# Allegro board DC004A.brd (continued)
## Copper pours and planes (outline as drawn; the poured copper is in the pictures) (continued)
5VIN on L06_PWR-1: 38.73,22.99 35.43,26.29 26.8,26.29 26.8,29.59 25.27,31.11 25.27,34.04 33.78,34.04 34.16,34.42 34.16,58.93 33.91,59.18 4.06,59.18 1.91,61.34 1.91,113.54 2.03,113.54 4.06,115.57 4.06,135.89 5.97,135.89 5.97,155.45 12.07,155.45 12.32,155.19 12.32,141.86 12.7,141.86 12.7,72.9 15.88,69.72 48.39,69.72 51.18,66.93 51.18,33.15 61.47,33.15 61.47,30.99 46.23,30.99 44.96,29.72 44.96,22.99
5VIN on L08_PWR-2: 26.43,30.1 25.53,30.1 25.53,33.15 25.97,33.15 26.15,33.33 26.15,33.5 36.67,33.5 38.17,32 40.64,32 45.21,27.43 45.21,5.71 36.96,5.71 36.95,5.72 36.95,25.11 27.24,25.11 26.43,25.92
+2.2V on TOP, L04_SIG-1: 67.44,23.11 62.36,23.11 61.21,24.26 61.21,27.3 62.99,27.3 62.99,25.53 63.25,25.27 67.56,25.27 67.56,27.56 64.64,27.56 64.64,28.96 67.56,28.96 67.56,33.02 70.74,36.2 70.74,37.97 72.9,40.13 77.34,40.13 77.47,40 77.47,34.04 73.53,34.04 73.53,28.19 77.09,28.19 77.09,22.9 75.56,22.9 75.56,19.81 67.44,19.81
+3.3V_LMX on TOP: 56.9,141.35 56.9,135.13 63.88,135.13 64.14,134.87 67.06,134.87 67.56,135.38 67.56,137.92 67.06,138.43 67.06,139.07 64.64,139.07 64.64,137.41 61.09,137.41 59.94,138.56 59.94,141.35
+3.3V_LMX on TOP: 37.34,133.35 37.34,128.78 40.51,128.78 40.51,133.35
+3.3V_LMX on L06_PWR-1: 46.1,140.72 53.21,140.72 54.99,142.49 56.77,142.49 59.94,145.67 63.63,145.67 63.63,141.73 63.25,141.35 59.94,141.35 59.94,138.56 61.09,137.41 64.64,137.41 64.64,139.07 67.06,139.07 67.06,138.43 67.56,137.92 67.56,135.89 66.8,135.13 52.96,135.13 52.96,135 47.5,135 40.51,128.02 36.2,128.02 36.2,130.81 ; 1 cut-out
+3.3V_LMX on L08_PWR-2: 62.61,133.6 60.58,135.64 58.42,135.64 57.91,136.14 57.91,137.03 57.52,137.42 57.52,139.92 56.51,140.93 55.57,140.93 55.25,141.25 55.25,143.76 56.87,145.39 71.88,145.39 71.88,133.6
+3.3V_LMXRF on TOP: 24.64,132.97 24.64,126.36 25.27,125.73 26.42,125.73 27.18,126.49 27.18,128.02 27.05,128.14 27.05,132.97
+3.3V_LMXRF on L06_PWR-1: 24.89,125.73 26.67,125.73 27.18,126.24 27.18,128.65 27.3,128.78 27.3,132.97 24.77,132.97 24.77,131.7 24.64,131.57 24.64,125.98
+3.3V_LMXRF on L08_PWR-2: 23.56,127.57 20.57,130.56 20.57,151.89 21.59,152.91 31.11,152.91 32.38,151.64 32.38,142.49 34.16,140.72 54.36,140.72 54.86,140.21 56.64,140.21 57.28,139.57 57.28,135.76 58.29,134.75 60.58,134.75 61.47,133.86 61.47,132.97 61.09,132.59 55.75,132.59 53.34,135 53.34,137.41 30.35,137.41 28.45,139.32 28.45,144.27 26.29,146.43 23.49,146.43 23.49,135.64 28.19,130.94 28.19,126.11 27.3,125.22 24.89,125.22 23.56,126.56
+3.3VCLK on TOP: 88.14,134.75 88.14,132.84 89.66,132.84 89.66,134.75
+3.3VCLK on TOP: 33.15,146.05 33.15,141.99 33.4,141.73 36.32,141.73 36.32,146.05
+3.3VCLK on TOP: 93.38,131.19 93.38,129.29 94.41,129.29 94.41,131.19
+3.3VCLK on TOP: 102.74,118.11 102.74,117.35 96.14,117.35 96.14,118.11
+3.3VCLK on TOP: 102.74,130.56 106.55,130.56 106.55,131.57 106.43,131.7 102.74,131.7
+3.3VCLK on TOP: 89.41,119.51 89.41,120.65 89.79,120.65 89.79,121.16 91.31,121.16 91.31,119.51
+3.3VCLK on L08_PWR-2: 87.12,113.66 87.12,119.25 87.01,119.37 87.01,124.74 85.87,125.88 77.32,125.88 77.22,125.98 77.22,127.51 77.47,127.76 77.47,139.87 80.14,142.54 80.14,143.76 80.14,143.76 80.14,146.05 46.23,146.05 41.53,141.35 33.91,141.35 33.15,142.11 33.15,146.05 34.54,147.45 36.45,147.45 43.31,154.31 85.47,154.31 93.81,145.96 105.37,145.96 108.71,142.62 108.71,123.7 107.82,122.81 107.82,113.66
GND on TOP (solid shape): 30.91,118.49 31.94,117.61 32.97,118.49 32.97,119 36.5,119 36.5,109.86 34.49,109.86 34.49,110.36 33.45,111.3 32.41,110.36 32.41,109.86 31.44,109.86 31.44,110.36 30.41,111.26 29.39,110.36 29.39,109.86 27.35,109.86 27.35,119 30.91,119
GND on TOP (solid shape): 29.36,81.15 30.4,80.22 31.44,81.15 31.44,81.66 32.26,81.66 33.4,80.24 34.54,81.66 36.5,81.66 36.5,72.52 32.94,72.52 32.94,73.03 31.91,73.91 30.88,73.03 30.88,72.52 27.35,72.52 27.35,81.66 29.36,81.66
GND on TOP: 60.45,141.22 60.45,137.67 63.88,137.67 63.88,141.22
GND on TOP: 12.95,146.18 12.95,156.08 21.08,156.08 21.08,153.04 23.75,153.04 23.75,151.77 21.08,151.77 21.08,146.18
GND on TOP: 7,42.48 7,41.84 9.35,41.84 9.35,42.48
GND on TOP: 39.24,2.03 39.24,3.43 38.48,4.19 38.48,7.62 40.39,7.62 40.39,6.6 46.61,6.6 46.61,14.99 43.18,14.99 43.18,16.26 55.37,16.26 55.37,2.03
GND on TOP: 1.27,37.59 1.27,42.55 9.4,42.55 9.4,37.59
GND on TOP: 94.51,128.8 94.51,128.73 94.14,128.36 94.14,120.97 94.23,120.87 95.19,120.87 95.54,121.22 102.28,121.22 102.45,121.39 102.45,122.02 101.98,122.49 101.98,128.82 94.53,128.82
GND on TOP: 80.26,21.97 80.26,23.75 83.57,23.75 83.57,32.64 92.96,32.64 92.96,21.97
GND on TOP: 39.24,18.03 39.24,21.72 38.35,21.72 38.35,23.75 40.51,23.75 40.51,22.61 46.61,22.61 46.61,30.99 43.18,30.99 43.18,32.26 55.37,32.26 55.37,18.03
GND on TOP: 13.72,131.95 13.72,141.86 21.84,141.86 21.84,138.81 24.51,138.81 24.51,137.54 21.84,137.54 21.84,131.95
GND on TOP: 0.38,47.24 0.38,49.45 0.38,49.45 0.38,54.36 9.27,54.36 9.27,47.24
GND on TOP: 80.26,0.89 80.26,2.67 83.57,2.67 83.57,11.56 92.96,11.56 92.96,0.89
GND on BOTTOM: 15.14,92.31 15.14,89.14 17.82,89.14 17.82,92.31
GND on BOTTOM: 25.48,88.54 25.48,90.83 27.97,90.83 27.97,101.52 29.97,101.52 29.97,102.97 33.86,102.97 33.86,101.52 36.2,101.52 36.2,100.46 39.45,100.46 39.45,101.52 40.97,101.52 40.97,100.2 39.57,100.2 39.57,90.37 39.04,90.37 39.04,90.02 33.76,90.02 33.76,88.54 ; 2 cut-outs
GND on BOTTOM: 40.67,100.81 40.67,103.3 41.17,103.3 41.17,103.94 43.76,103.94 43.76,102.82 42.01,102.82 42.01,100.81
GND on BOTTOM: 55.58,64.7 55.58,57.79 62.12,57.79 62.12,57.79 63.92,57.79 63.92,59.38 62.12,59.38 62.12,64.7 59.52,64.7 59.52,65.38 58.68,65.38 58.68,64.7
GND on L02_GND-1: 0.38,22.9 0.38,35.94 0.38,35.94 0.38,36.58 0.38,36.58 0.38,49.56 0,49.94 0,115.29 0.38,115.67 0.38,147.83 0.38,147.83 0.38,156.72 111.76,156.72 111.76,156.71 111.76,119.63 149.48,119.63 149.48,52.07 111.87,52.07 111.87,22.9 111.89,22.88 111.89,0.51 111.76,0.38 0.38,0.38 0.38,22.9 ; 20 cut-outs
GND on L03_GND-2: 0.38,49.53 0,49.91 0,115.29 0.38,115.67 0.38,147.83 0.38,147.83 0.38,156.59 111.63,156.59 111.76,156.46 111.76,119.63 149.48,119.63 149.48,52.07 111.92,52.07 111.92,0.41 111.89,0.38 0.51,0.38 0.38,0.51 0.38,0.51 ; 4 cut-outs
GND on L04_SIG-1: 37.34,86.23 36.99,86.58 36.99,93.4 37.78,94.2 37.78,99.32 36.71,100.39 36.71,102.81 36.86,102.96 36.83,103 36.83,104.65 37.21,105.03 40.87,105.03 43.81,102.09 43.81,88.77 41.28,86.23 ; 1 cut-out
GND on L05_GND-3: 0.38,49.61 0,49.99 0,115.29 0.38,115.67 0.38,147.83 0.38,147.83 0.38,156.59 111.76,156.59 111.76,119.63 149.48,119.63 149.48,52.07 111.92,52.07 111.92,0.67 111.89,0.63 0.64,0.63 0.38,0.89 ; 4 cut-outs
GND on L06_PWR-1: 116.46,53.34 116.46,55.88 80.9,55.88 80.9,94.61 47.88,94.61 47.88,107.95 19.3,107.95 19.3,122.55 47.88,122.55 47.88,129.54 70.1,129.54 70.1,147.32 38.35,147.32 38.35,156.21 111.38,156.21 111.38,118.75 149.48,118.75 149.48,53.34 ; 1 cut-out
GND on L07_GND-4: 0.38,49.53 0,49.91 0,115.29 0.38,115.67 0.38,147.83 0.38,147.83 0.38,156.59 111.63,156.59 111.76,156.46 111.76,119.63 149.48,119.63 149.48,52.07 111.92,52.07 111.92,0.41 111.89,0.38 0.51,0.38 0.38,0.51 0.38,0.51 ; 2 cut-outs
GND on L08_PWR-2: 117.6,52.83 117.6,78.74 90.42,78.74 90.42,111.12 117.6,111.12 117.6,118.87 149.1,118.87 149.1,52.83
GND on L08_PWR-2: 5.33,156.21 5.33,132.08 19.3,132.08 19.3,156.21
GND on L08_PWR-2: 47.24,1.27 47.24,29.21 53.59,29.21 53.59,1.27
GND on L08_PWR-2: 2.03,37.97 2.03,53.85 1.91,53.85 1.91,119.25 26.04,119.25 26.04,101.22 24.77,101.22 24.77,99.19 26.04,99.19 26.04,58.59 15.73,58.59 15.73,53.65 13.21,53.65 13.21,37.97
GND on L08_PWR-2: 0.89,22.22 0.89,0.63 35.81,0.63 35.81,22.22
GND on L09_GND-5: 0.38,49.61 0,49.99 0,115.29 0.38,115.67 0.38,147.83 0.38,147.83 0.38,156.59 111.76,156.59 111.76,119.63 149.48,119.63 149.48,52.07 111.92,52.07 111.92,0.67 111.89,0.63 0.64,0.63 0.38,0.89 ; 2 cut-outs
GND on L10_SIG-2: 37.78,99.32 37.78,94.2 36.99,93.4 36.99,86.58 37.34,86.23 41.28,86.23 43.81,88.77 43.81,102.09 42.77,103.13 42.53,103.37 41.4,103.37 40.88,103.89 37.72,103.89 37.72,103.88 37.21,103.37 36.84,103.37 36.83,103.38 36.83,103 36.86,102.96 36.71,102.81 36.71,100.39
GND on L11_GND-6: 0.38,49.6 0,49.98 0,115.29 0.38,115.67 0.38,147.83 0.38,147.83 0.38,156.72 111.76,156.72 111.76,156.71 111.76,119.63 149.48,119.63 149.48,52.07 111.92,52.07 111.92,0.54 111.76,0.38 0.38,0.38 0.38,0.38 ; 4 cut-outs
VBUS on TOP: 18.31,37.49 24.92,37.49 25.02,37.39 25.02,36.05 25.5,35.58 25.5,34.71 26.68,33.52 33.48,33.52 34.39,34.43 34.39,37.1 34.11,37.38 32.74,37.38 32.65,37.29 32.65,35.56 32.47,35.37 31.69,35.37 31.38,35.68 31.38,37.2 31.32,37.25 30.75,37.25 30.62,37.13 30.62,36.51 29.8,35.69 27.81,35.69 27.81,35.69 27.05,35.69 26.54,36.2 26.54,37.47 26.55,37.47 26.55,38.99 25.93,39.61 18.73,39.61 18.31,39.19
VDDD33 on TOP: 24.13,146.05 24.13,141.22 26.54,141.22 26.54,146.05
VDDD33 on TOP: 107.59,66.56 107.59,64.05 106.81,63.27 106.81,62.39 106.91,62.29 109.04,62.29 109.06,62.31 109.06,66.33 108.84,66.56
VDDD33 on TOP: 42.8,39.37 42.8,41.27 50.04,41.27 50.04,40 44.32,40 44.32,39.37
VDDD33 on L08_PWR-2: 70.74,103.25 63.5,110.49 52.2,110.49 41.66,121.03 41.66,125.6 43.05,125.6 43.94,124.71 45.85,124.71 45.85,126.36 44.58,127.64 38.48,127.64 37.97,127.13 32.64,127.13 32.64,121.28 27.43,121.28 27.05,120.9 24.26,120.9 23.88,121.28 5.71,121.28 5.71,128.65 6.86,129.79 19.18,129.79 21.08,127.89 28.7,127.89 28.7,131.19 24,135.89 24,145.92 24.07,145.99 25.97,145.99 28.07,143.89 28.07,139.19 30.1,137.16 34.04,137.16 35.05,136.14 40.89,136.14 56.39,120.65 56.39,120.52 74.93,120.52 74.93,120.4 78.61,120.4 85.22,113.79 85.22,77.09 111,77.09 111,57.66 85.85,57.66 85.85,63.88 85.6,64.14 78.87,64.14 78.36,63.63 78.36,61.34 77.34,60.32 77.34,58.29 76.71,57.66 75.44,57.66 70.48,52.7 52.71,52.7 52.71,44.32 52.58,44.2 46.36,44.2 45.47,43.31 45.47,41.91 49.91,41.91 49.91,40.39 49.78,40.26 45.47,40.26 45.47,36.96 46.1,36.32 46.1,34.99 43.37,34.99 41.15,37.21 41.15,49.78 44.96,53.59 45.47,53.59 45.47,63.88 45.59,64.01 48.01,64.01 49.53,65.53 49.53,70.61 50.04,71.12 70.74,71.12 ; 61 cut-outs
VDDD33 on L10_SIG-2: 73.99,69.27 73.99,67.45 74.76,67.45 74.76,69.27
VDDL19 on TOP: 84.96,38.35 84.96,40.51 83.44,40.51 83.44,42.16 87.88,42.16 87.88,40.51 87,40.51 87,38.35
VDDL19 on BOTTOM: 47.12,39.62 47.12,38.73 49.53,38.73 49.53,39.62
VDDL19 on L04_SIG-1: 87.55,71.94 87.55,68.09 83.51,64.06 83.51,61.54 82.66,60.69 80.6,60.69 80.14,61.15 80.14,62.61 80.16,62.63 80.16,64.23 80.15,64.23 80.15,65.53 78.55,67.14 77.25,67.14 75.84,68.54 74.32,68.54 73.67,67.89 72.44,67.89 72.32,68.02 72.32,70.68 73.37,71.73 74.93,71.73 75.45,71.21 80.54,71.21 81.5,72.17 81.53,72.14 87.35,72.14
VDDL19 on L08_PWR-2: 46.1,40 50.04,40 52.45,42.42 78.99,42.42 78.99,61.34 80.52,62.87 85.22,62.87 85.22,45.59 87.76,43.05 87.76,38.23 86.11,38.23 85.47,38.86 82.8,38.86 81.79,37.85 61.98,37.85 61.09,38.73 52.96,38.73 51.56,37.34 46.1,37.34
VDDL19 on L10_SIG-2: 72.78,71.08 72.78,69.19 74.06,69.19 74.06,71.08
VINA on TOP (solid shape): 32.24,120.9 32.12,120.86 32.06,120.74 32.06,120.61 31.79,120.61 31.79,120.74 31.73,120.86 31.61,120.9 31.61,123.7 32.24,123.7
VINB on TOP (solid shape): 32.06,70.77 32.12,70.66 32.24,70.61 32.24,67.82 31.61,67.82 31.61,70.61 31.73,70.66 31.79,70.77 31.79,70.91 32.06,70.91
1P8V_USB on BOTTOM: 62.48,63.51 62.48,65.41 59.94,65.41 59.94,65.69 58.05,65.69 58.05,65.41 54.48,65.41 54.48,69.22 63.75,69.22 63.75,65.53 66.67,65.53 66.67,59.56 63.13,59.56 63.13,63.51
1P8V_USB on L10_SIG-2: 50.14,69.22 64.94,69.22 66.72,67.44 66.72,59.25 65.46,57.99 51.66,57.99 49.36,60.3 49.36,68.43 ; 4 cut-outs
12P0V_RX on TOP: 140.11,68.16 140.11,64.7 141.41,64.7 141.41,68.16
DEVCLKIN on TOP (solid shape): 5.13,97.23 5.24,97.17 5.38,97.17 5.38,96.89 5.24,96.89 5.13,96.83 5.08,96.71 2.29,96.71 2.29,97.35 5.08,97.35
DEVCLKIN on TOP (solid shape): 15.98,96.65 14.86,96.65 14.74,96.82 14.53,96.89 14.52,96.89 14.52,97.17 14.53,97.17 14.74,97.23 14.86,97.41 15.98,97.41
MASTER_BYPASS on TOP, L04_SIG-1: 79.76,39.75 79.76,35.18 83.31,35.18 83.31,39.75
MASTER_BYPASS1 on L06_PWR-1: 80.9,44.96 88.52,44.96 88.52,43.94 80.9,43.94
SLAVE_BYPASS on L04_SIG-1: 80.01,15.49 80.01,18.54 83.06,18.54 83.06,14.22 77.72,14.22 77.72,15.49
SLAVE_BYPASS1 on TOP, L04_SIG-1: 85.09,14.86 90.93,14.86 90.93,17.4 89.53,17.4 89.53,18.92 92.2,18.92 92.2,13.08 85.09,13.08
V_BUS on BOTTOM: 26.92,40.77 26.92,37.72 30.35,37.72 30.35,40.77
V_BUS on L04_SIG-1: 26.88,40.58 26.88,37.83 30.23,37.83 30.23,40.58
VA11 on TOP, L08_PWR-2: 85.09,15.11 85.09,18.8 83.44,18.8 83.44,20.83 87.88,20.83 87.88,19.81 87,19.81 87,16.64 88.01,16.64 88.01,15.11
VA11 on BOTTOM: 15.37,85.6 19.94,85.6 19.94,87.88 18.41,87.88 18.41,88.52 15.37,88.52
VA11 on L06_PWR-1: 63.37,71.55 59.68,75.24 44.79,75.24 43.44,73.9 16.63,73.9 13.71,76.81 13.71,104.78 15.15,106.22 34.05,106.22 36.1,104.17 36.07,104.14 36.07,92.2 36.58,91.69 41.58,91.69 41.58,90.67 42.59,89.66 76.08,89.66 78.36,87.38 78.36,37.5 77.6,36.74 77.6,25.27 81.15,21.72 88.01,21.72 88.01,15.24 73.47,15.24 73.06,15.65 73.06,15.97 64.26,24.77 64.26,31.88 63.37,32.77 ; 5 cut-outs
VA19 on TOP: 94.74,40.51 94.74,36.32 97.66,36.32 97.66,49.78 80.64,49.78 80.64,47.75 80.77,47.62 94.87,47.62 94.87,40.51
VA19 on BOTTOM: 29.15,88.13 26.8,88.13 26.8,84.87 29.15,84.87
VA19 on L06_PWR-1: 16.38,47.12 24.38,47.12 24.38,46.99 29.59,46.99 29.59,42.42 24.38,42.42 24.38,14.73 90.17,14.73 90.17,20.45 92.84,23.11 92.84,34.16 94.87,36.2 94.87,47.62 80.64,47.62 80.64,50.29 99.19,50.29 103.25,46.23 103.25,5.97 99.7,5.97 99.44,6.22 17.27,6.22 16.38,7.11
VA19 on L08_PWR-2: 37.72,126.75 37.72,103.89 34.29,100.46 34.29,94.08 33.66,93.45 33.66,91.19 35.31,89.53 35.31,70.23 30.86,65.79 30.86,58.17 30.99,58.04 30.99,44.45 26.67,44.45 26.67,99.44 25.02,99.44 25.02,100.84 26.67,100.84 26.67,117.22 32.89,123.44 32.89,126.75 ; 3 cut-outs
VA19 on L08_PWR-2: 94.74,40.69 94.89,40.84 94.89,42.67 96.28,44.05 97.66,44.05 97.66,36.32 96.01,36.32 95.63,36.7 95.63,37.47 94.74,37.47
VADJ_RX on L10_SIG-2: 132.22,63.2 132.22,59.95 140.29,59.95 140.29,63.2
VD11 on TOP: 94.74,19.68 94.74,15.37 97.54,15.37 97.54,19.68
VD11 on L08_PWR-2: 94.74,15.37 94.74,16.64 89.41,16.64 89.41,21.08 89.15,21.34 66.67,21.34 63.88,24.13 63.88,31.37 62.23,33.02 58.04,33.02 55.88,30.86 43.43,30.86 41.78,32.51 38.61,32.51 32.13,38.99 32.13,64.64 32.26,64.64 36.7,69.09 36.7,88.7 34.21,91.19 34.21,93.9 34.42,94.11 34.44,94.11 34.8,94.46 34.8,99.41 38.23,102.84 38.23,126.75 38.73,127.25 44.45,127.25 45.59,126.11 45.59,125.35 45.53,125.41 44.13,125.41 43.69,125.86 41.15,125.86 41.15,120.7 44.12,117.73 44.12,106.95 51.17,99.9 51.17,73.79 48.64,71.26 48.64,68.96 38.99,59.31 38.99,38.23 42.8,34.42 48.01,34.42 50.29,36.7 69.09,36.7 71.25,34.54 88.27,34.54 94.74,28.07 94.74,25.4 95.25,24.89 95.5,24.89 97.66,22.73 97.66,16.64 97.54,16.64 97.54,15.37 ; 1 cut-out
VIO_B_M2C_RX on TOP: 130.8,59.56 132.47,59.56 132.47,61.31 133.5,62.33 133.5,63.16 131.19,63.16 130.8,62.77
VPHY on BOTTOM: 52.75,65.02 52.95,64.82 52.95,63.87 53.13,63.68 54.85,63.68 54.95,63.78 54.95,64.74 54.79,64.9 54.16,64.9 54.02,65.04 54.02,66 53.9,66.12 52.78,66.12 52.75,66.09
N19884870 on TOP, BOTTOM: 76.18,130.65 76.81,130.65 76.84,130.63 76.84,127.48 78.59,127.48 78.59,130.27 77.95,130.91 77.95,132.84 77.98,132.87 77.98,134.11 76.2,134.11 76.18,134.09
N19887756 on TOP: 91.8,127.71 91.8,130.37 91.67,130.37 91.67,130.25 90.27,130.25 90.27,134.06 91.67,134.06 91.67,131.39 92.56,131.39 92.56,127.71
N19887756 on TOP: 91.42,126.94 91.42,123.39 91.29,123.26 90.15,123.26 90.15,126.94
N19887756 on L10_SIG-2: 90.02,125.17 90.02,134.06 92.81,134.06 92.81,125.17
N19887760 on TOP: 94.78,130.5 94.78,129.35 96.67,129.35 96.67,130.86 95.14,130.86
N19887762 on TOP: 101.32,131.58 101.32,129.38 102.19,129.38 102.19,131.58
N19887836 on TOP: 91.82,123.01 91.82,120.43 93.77,120.43 93.77,123.01
N19887836 on L10_SIG-2: 91.27,119.7 91.27,123.69 93.7,123.69 93.7,121.1 102.08,121.1 102.08,124.66 104.75,124.66 104.75,119.7
N19887910 on TOP: 99.21,120.78 99.21,118.61 100.41,118.61 100.41,120.78
N19887912 on TOP: 101.48,120.74 101.48,118.74 102.75,118.74 102.75,120.74
N19887930 on TOP: 95.75,120.74 95.75,118.62 97.83,118.62 97.83,120.74
N20392160 on TOP: 17.49,37.69 17.49,38.83 15.95,38.83 15.45,39.34 15.37,39.34 15.37,44.2 15.24,44.32 14.1,44.32 13.08,43.31 13.08,38.68 13.82,37.95 14.08,37.69
N20392160 on BOTTOM: 7.25,45.89 7.25,45.85 7.24,45.85 6.98,45.59 6.98,43.32 7.25,43.05 11.94,43.05 12.83,42.16 12.83,37.95 15.3,37.95 15.49,38.15 15.49,39.37 15.37,39.37 15.37,44.36 14.77,44.36 12.69,46.43 7.79,46.43
N20560674 on TOP: 138.64,66.52 138.3,66.52 138.3,59.56 139.91,59.56 140.96,60.62 140.96,63.39 140.84,63.52 140.28,63.52 139.74,64.06 139.74,66.45 139.46,66.73 138.85,66.73
N20770678 on TOP: 77.85,10.41 82.04,10.41 82.04,4.45 80.39,4.45 80.39,5.84 77.34,5.84 77.34,6.1 73.66,6.1 73.66,8.13 77.85,8.13
N20770678 on L08_PWR-2: 73.66,6.1 73.66,8.13 77.85,8.13 77.85,10.41 82.04,10.41 82.04,4.45 80.39,4.45 80.39,5.84 77.22,5.84 77.22,6.1
N20770710 on TOP, L08_PWR-2: 98.42,2.92 98.42,4.45 95.12,4.45 95.12,9.14 98.55,9.14 98.55,11.43 107.19,11.43 107.19,10.16 99.7,10.16 99.7,6.6 103,6.6 103,1.14 101.47,1.14 101.47,2.92
N20770834 on TOP, L08_PWR-2: 95.12,10.79 95.12,14.48 98.81,14.48 98.81,12.83 98.17,12.83 98.17,10.79
N20771385 on TOP, L08_PWR-2: 56.9,3.3 56.9,9.27 58.67,9.27 58.67,6.6 64.14,6.6 64.14,3.3
N20772352 on TOP: 57.53,18.8 57.53,25.15 58.8,25.15 58.8,22.61 64.01,22.61 64.01,18.8
N20772352 on L08_PWR-2: 57.53,18.8 64.01,18.8 64.01,22.61 58.55,22.61 58.55,25.4 57.53,25.4
N20774965 on TOP, L08_PWR-2: 80.01,25.78 80.01,27.3 78.99,27.3 78.99,28.19 80.01,28.19 80.01,31.37 82.04,31.37 82.04,25.78
N20775020 on TOP, L08_PWR-2: 98.42,24.89 98.42,25.65 95.25,25.65 95.25,30.1 98.3,30.1 98.3,31.37 98.55,31.37 98.55,32.77 99.57,32.77 99.57,27.81 101.6,27.81 101.6,22.61 100.46,22.61 100.46,24.89
N20775144 on TOP, L08_PWR-2: 94.87,31.88 94.87,33.27 96.65,33.27 96.65,35.69 99.19,35.69 99.19,34.29 98.3,34.29 98.3,31.88
N20776452 on TOP, L08_PWR-2: 89.41,37.97 89.41,43.56 90.42,43.56 90.42,40.39 92.58,40.39 92.58,37.97

Small or netless copper shapes (teardrops, artwork), in the pictures only: 2 on TOP, 6 on L11_GND-6

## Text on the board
BOTTOM: LAYER 12 (BOTTOM SIDE)
Board Geometry/Soldermask Bottom: SOLDERMASK BOTTOM
Ref Des/Silkscreen Bottom: GND | LMX2582 | LMK04832 | SILKSCREEN BOTTOM
User.Comments: TEXAS INSTRUMENTS, INC. | ADC12DJ3200EVMCVAL REV A | DC004 | SEE NOTE 16
TOP: LAYER 1 (TOP SIDE)
Board Geometry/Soldermask Top: SOLDERMASK TOP
Ref Des/Silkscreen Top: PRSNT_M2C_L | ADC12DJ3200CVAL-SP | ROHS EXEMPT | TDI | TDO | DC-004 | SILKSCREEN TOP
L02_GND-1: LAYER 2 - GND
L03_GND-2: LAYER 3 - GND
L04_SIG-1: LAYER 4 - SIG-1
L05_GND-3: LAYER 5 - GND
L06_PWR-1: LAYER 6 - PWR-1
L07_GND-4: LAYER 7 - GND
L08_PWR-2: LAYER 8 - PWR-2
L09_GND-5: LAYER 9 - GND
L10_SIG-2: LAYER 10 - SIG-2
L11_GND-6: LAYER 11 - GND
PAGE_OUTLINE: PASTEMASK TOP
DIMENSION: PASTEMASK BOTTOM
ASSEMBLY_DETAIL1: SEE NOTE 3 | TOP VIEW | BOTTOM VIEW
User.6: SOLDERMASK TOP SOCKET BOARD
User.7: PASTEMASK TOP SOCKET BOARD
User.9: TRACE WIDTH | (MILS) | TOL | (%) | SPACING | IMPEDANCE TABLE. | L01_TOP | L04_SIG-1 | L10_SIG-2 | L12_BOTTOM | 50 OHM SINGLE ENDED | 5.5 | 6.5 | 11 | 5 % | 4.9 | 6 | 100 OHM DIFFERENTIAL | TIGHTLY COUPLED | 7.1 | 5 | NIL | 6.3 | 10 | LOOSELY COUPLED | 20.1 | 18
User.14: 11-11-15 | 3. MARK BOARD'S SILKSCREEN WITH THE APPROPRIATE EVM PART NUMBER AND SERIAL NUMBER. | 4. IPC-A-610 / ACCEPTABILITY OF ELECTRONIC ASSEMBLIES, CLASS2, CURRENT REVISION. | DC004
User.26: FIGURE | SIZE | 8.0 | 10.0 | 12.0 | 13.0 | 15.0 | 38.0 | 40.0 | 59.0 | 62.0 | 63.0 | 67.0 | 106.0 | 120.0 | 125.0 | 140.0 | 39.0 | 50.0 | DRILL CHART: TOP to BOTTOM | ALL UNITS ARE IN MILS | PLATED | NON-PLATED | QTY | 7 | 2110 | 56 | 16 | 236 | 39 | 26 | 14 | 2 | 8 | 1
User.36: 2.0 MIL | 6.00 MIL | 2.00 MIL | 5.6 MIL | 5.00 MIL | 7.6  MIL | 4.00 MIL | 3.7 MIL | 3.00 MIL | 7.6 MIL | THIS IS A 12 LAYER BOARD | LAYER STACK-UP | MEGTRON 6 | LAYER 1 TOP | LAYER 2 GND-1 | LAYER 3 GND-2 | LAYER 4 SIG-1 | LAYER 5 GND-3 | LAYER 6 PWR-1 | LAYER 7 GND-4 | LAYER 8 PWR-2 | LAYER 9 GND-5 | LAYER 10 SIG-2 | LAYER 11 GND-6 | LAYER 12 BOTTOM
